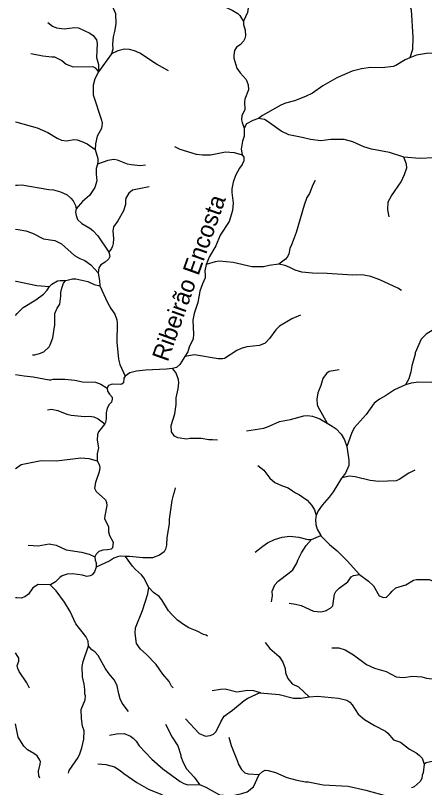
# Model space of a CAD drawing. Extents: x 500 to 555.2, y 9115.7 to 9171.
# Drawn here: x 500 to 504.79, y 9143.26 to 9152.3 of the extents above; entities that cross this region are included whole.
import ezdxf
from ezdxf.enums import TextEntityAlignment as Align

# ---------------------------------------------------------------- set-up
doc = ezdxf.new("R2010")
doc.units = 0
doc.header["$LTSCALE"] = 0.064
doc.layers.add('61', color=7, linetype='Continuous')
doc.layers.add('7', color=7, linetype='Continuous', lineweight=25)

msp = doc.modelspace()

# ---------------------------------------------------------------- linework, layer by layer
at = {"layer": '7'}
for points in [[(500.9676, 9152.7694), (500.9701, 9152.7268), (500.9891, 9152.6569), (501.0168, 9152.5919), (501.1328, 9152.412), (501.1707, 9152.3228), (501.174, 9152.2009), (501.1611, 9152.1136), (501.1443, 9152.0512), (501.1349, 9151.966), (501.1379, 9151.9062), (501.1255, 9151.8512), (500.9703, 9151.6416)], [(501.9827, 9152.5119), (502.1534, 9152.577), (502.2129, 9152.5851), (502.2481, 9152.5782), (502.3137, 9152.5347), (502.4061, 9152.4214), (502.5362, 9152.3619), (502.6017, 9152.3224), (502.6273, 9152.2997), (502.6672, 9152.2303)], [(502.7408, 9152.507), (502.7145, 9152.3334), (502.6671, 9152.2321), (502.6672, 9152.2303)], [(504.5928, 9152.4699), (504.6303, 9152.3683), (504.6515, 9152.0479), (504.6464, 9151.9023), (504.6152, 9151.8029)], [(500.3777, 9152.2187), (500.4333, 9152.1733), (500.4787, 9152.154), (500.57, 9152.1426), (500.6954, 9152.1587), (500.7376, 9152.1538), (500.8713, 9152.0921), (500.9084, 9152.0668), (500.949, 9152.0133), (500.9573, 9151.9733), (500.9479, 9151.8073), (500.9737, 9151.7273), (500.9703, 9151.6416)], [(502.6672, 9152.2303), (502.6701, 9152.195), (502.6866, 9152.1287), (502.6911, 9152.0622), (502.6848, 9152.031), (502.668, 9152.0008), (502.63, 9151.9568), (502.5882, 9151.9274), (502.5635, 9151.8891), (502.5553, 9151.834), (502.5573, 9151.8001), (502.5924, 9151.6845), (502.6283, 9151.6302), (502.6994, 9151.5501), (502.7242, 9151.4883), (502.7257, 9151.4296), (502.6839, 9151.3205), (502.6787, 9151.289), (502.6863, 9151.1944), (502.6508, 9151.1274), (502.6473, 9151.0777)], [(501.7905, 9151.6527), (501.6488, 9151.7315), (501.4538, 9151.8598), (501.3929, 9151.8879), (501.3337, 9151.9026), (501.2778, 9151.9054), (501.1966, 9151.8862), (501.1255, 9151.8512)], [(500.1783, 9151.8533), (500.3212, 9151.8275), (500.4262, 9151.8161), (500.4574, 9151.8174), (500.5426, 9151.7717), (500.5936, 9151.7308), (500.6762, 9151.6983), (500.907, 9151.7012), (500.9325, 9151.6879), (500.9703, 9151.6416)], [(504.6152, 9151.8029), (504.5628, 9151.7813), (504.4519, 9151.7147), (504.4194, 9151.7046), (504.2913, 9151.6866), (504.1548, 9151.6895), (504.0498, 9151.6762), (503.9417, 9151.6497), (503.7622, 9151.5706), (503.5986, 9151.4764), (503.4766, 9151.3919), (503.3965, 9151.3524), (503.2645, 9151.2996), (503.1589, 9151.273), (503.1064, 9151.2517), (502.8904, 9151.1301), (502.8449, 9151.0937)], [(505.002, 9151.8631), (504.8109, 9151.8553), (504.6949, 9151.8358), (504.6152, 9151.8029)], [(500.9703, 9151.6416), (500.9283, 9151.5569), (500.9112, 9151.4854), (500.9085, 9151.3722), (501.0066, 9151.0736), (501.0134, 9151.0395), (501.0069, 9150.9753), (500.9561, 9150.8859), (500.9363, 9150.7967), (500.9345, 9150.7305)], [(502.6473, 9151.0777), (502.6523, 9151.046), (502.6757, 9150.9804)], [(502.8449, 9151.0937), (502.8437, 9151.0927), (502.7779, 9151.0692), (502.7035, 9151.0316), (502.6757, 9150.9804)], [(504.5464, 9150.6424), (504.5436, 9150.6427), (504.3793, 9150.6973), (504.1668, 9150.7341), (504.0768, 9150.7628), (503.9479, 9150.822), (503.8453, 9150.8463), (503.6904, 9150.8498), (503.573, 9150.8336), (503.4528, 9150.8468), (503.3563, 9150.8718), (503.1984, 9150.9024), (503.1087, 9150.9447), (502.9473, 9151.0631), (502.9129, 9151.081), (502.8449, 9151.0937)], [(499.9999, 9151.0557), (500.0144, 9151.0516), (500.2529, 9150.9841), (500.3803, 9150.9285), (500.488, 9150.8627), (500.5371, 9150.8403), (500.5968, 9150.8335), (500.688, 9150.8466), (500.7214, 9150.8433), (500.778, 9150.8261), (500.8382, 9150.7965), (500.9345, 9150.7305)], [(502.6757, 9150.9804), (502.6759, 9150.9798), (502.6764, 9150.8886), (502.6569, 9150.8296), (502.6407, 9150.735), (502.6545, 9150.6698)], [(505.423, 9150.9952), (505.3829, 9150.9655), (505.2722, 9150.9271), (505.2438, 9150.9105), (505.1424, 9150.8142), (505.0532, 9150.702), (505.0118, 9150.6693), (504.9632, 9150.6482), (504.9035, 9150.6352), (504.7294, 9150.6237), (504.5464, 9150.6424)], [(500.9345, 9150.7305), (500.9632, 9150.624), (500.9647, 9150.5935), (500.9596, 9150.5602)], [(501.8611, 9150.7678), (501.9222, 9150.7335), (502.1164, 9150.6782), (502.1906, 9150.668), (502.2836, 9150.6703), (502.4601, 9150.7055), (502.5593, 9150.6939), (502.6545, 9150.6698)], [(501.5228, 9150.5473), (501.4629, 9150.5415), (501.3526, 9150.5511), (501.3125, 9150.561), (501.1932, 9150.6057), (501.1519, 9150.6135), (501.08, 9150.6032), (500.9596, 9150.5602)], [(502.6545, 9150.6698), (502.6717, 9150.6429), (502.6717, 9150.599), (502.6526, 9150.5559), (502.6226, 9150.512), (502.5764, 9150.4261), (502.547, 9150.3473), (502.5324, 9150.2692), (502.5324, 9150.2291), (502.5471, 9150.1019), (502.5403, 9150.016), (502.5002, 9149.8872), (502.3971, 9149.7264), (502.3463, 9149.6017), (502.2707, 9149.4768), (502.2323, 9149.384)], [(504.3736, 9149.9422), (504.358, 9150.0251), (504.3628, 9150.1177), (504.4015, 9150.1894), (504.5144, 9150.3507), (504.5527, 9150.4386), (504.5792, 9150.5172), (504.5775, 9150.5587), (504.5464, 9150.6424)], [(500.9596, 9150.5602), (500.9437, 9150.5101), (500.9446, 9150.4438), (500.9542, 9150.365), (500.9284, 9150.2862), (500.8647, 9150.1942), (500.7834, 9150.1211), (500.7111, 9150.0378)], [(503.5091, 9150.3673), (503.4793, 9150.3179), (503.441, 9150.2173), (503.4114, 9150.1686), (503.3774, 9150.08), (503.2837, 9149.7598), (503.2487, 9149.6672), (503.2313, 9149.6139), (503.2113, 9149.5698), (503.1998, 9149.5049), (503.1819, 9149.4721), (503.1589, 9149.4459), (503.0828, 9149.3887)], [(499.9999, 9150.3125), (500.0242, 9150.3138), (500.0743, 9150.3165), (500.3895, 9150.2633), (500.4459, 9150.2593), (500.527, 9150.237), (500.6033, 9150.2003), (500.6499, 9150.162), (500.6771, 9150.1296), (500.7014, 9150.0762), (500.7111, 9150.0378)], [(501.5656, 9150.2941), (501.3688, 9150.2547), (501.325, 9150.2211), (501.2926, 9150.1614), (501.2874, 9150.1342), (501.2888, 9150.0872), (501.2652, 9150.0116), (501.1977, 9149.8961), (501.1485, 9149.8249), (501.1414, 9149.7786), (501.1479, 9149.6892), (501.1444, 9149.6289), (501.1365, 9149.5974), (501.1243, 9149.5697), (501.0943, 9149.5292)], [(500.7111, 9150.0378), (500.7036, 9149.9961), (500.7101, 9149.9576), (500.727, 9149.9131), (500.7778, 9149.8653), (500.8718, 9149.8087), (500.9063, 9149.7809), (500.9636, 9149.7183), (501.0943, 9149.5292)], [(499.9999, 9149.7986), (500.0303, 9149.794), (500.1217, 9149.7801), (500.1992, 9149.7495), (500.3273, 9149.6833), (500.4623, 9149.6638), (500.5404, 9149.6281), (500.6925, 9149.4881), (500.7517, 9149.4538), (500.8106, 9149.4306), (500.882, 9149.3813), (500.9675, 9149.2848)], [(501.0943, 9149.5292), (501.1032, 9149.4761), (501.0908, 9149.4469), (501.0492, 9149.4098), (500.9991, 9149.3816), (500.9744, 9149.3467), (500.9675, 9149.2848)], [(502.2323, 9149.384), (502.2159, 9149.3119), (502.2206, 9149.2588), (502.2185, 9149.2286), (502.1894, 9149.1589), (502.1572, 9149.0732), (502.135, 9148.9392), (502.0926, 9148.8087), (502.0767, 9148.732), (502.0853, 9148.5692), (502.0795, 9148.5129), (502.0342, 9148.4171), (502.0185, 9148.3626), (501.9831, 9148.308)], [(503.0828, 9149.3887), (502.9687, 9149.3736), (502.9024, 9149.3556), (502.7668, 9149.3586), (502.5461, 9149.4063), (502.3852, 9149.4229), (502.3383, 9149.4162), (502.2323, 9149.384)], [(504.5195, 9149.0783), (504.4738, 9149.1065), (504.2644, 9149.2063), (504.1596, 9149.244), (504.077, 9149.2588), (503.9955, 9149.2636), (503.943, 9149.2605), (503.6483, 9149.2801), (503.4759, 9149.2818), (503.3519, 9149.2949), (503.2717, 9149.3171), (503.2102, 9149.3511), (503.1562, 9149.3734), (503.0828, 9149.3887)], [(500.9675, 9149.2848), (500.9671, 9149.2814), (500.9837, 9149.1971), (500.9892, 9149.1336)], [(499.9999, 9149.1893), (500.0085, 9149.1875), (500.2487, 9149.1378), (500.3992, 9149.1249)], [(500.1982, 9148.3278), (500.2285, 9148.3279), (500.2818, 9148.3403), (500.3306, 9148.363), (500.3951, 9148.4207), (500.4081, 9148.4419), (500.4392, 9148.524), (500.4556, 9148.654), (500.4622, 9148.6722), (500.4605, 9148.8098), (500.4884, 9148.8744), (500.5196, 9148.9217), (500.5311, 9149.015), (500.5309, 9149.0567), (500.5412, 9149.1079), (500.5638, 9149.1638), (500.5882, 9149.1968)], [(500.3992, 9149.1249), (500.4018, 9149.1291), (500.4276, 9149.1539), (500.4929, 9149.1928), (500.5221, 9149.1981), (500.5882, 9149.1968)], [(500.5882, 9149.1968), (500.6684, 9149.2159), (500.705, 9149.2145), (500.8488, 9149.1868), (500.9199, 9149.1516), (500.9892, 9149.1336)], [(499.9999, 9148.7879), (500.0206, 9148.8098), (500.0888, 9148.8818), (500.2374, 9148.971), (500.3265, 9149.0378), (500.3728, 9149.0823), (500.3992, 9149.1249)], [(500.9892, 9149.1336), (501.0782, 9148.9392), (501.1171, 9148.8679), (501.1617, 9148.8014), (501.1856, 9148.7372), (501.1923, 9148.6968), (501.1879, 9148.4754), (501.2071, 9148.2764), (501.2233, 9148.2124), (501.2827, 9148.0783)], [(503.3352, 9148.7913), (503.235, 9148.7473), (503.091, 9148.6625), (503.046, 9148.6206), (502.9739, 9148.5163), (502.9218, 9148.4644), (502.8572, 9148.435), (502.7067, 9148.4189), (502.6416, 9148.3996), (502.5905, 9148.3757), (502.4476, 9148.2825), (502.4221, 9148.2779), (502.3736, 9148.2809), (502.0973, 9148.327), (501.9831, 9148.308)], [(505.1435, 9148.6389), (505.102, 9148.636), (505.042, 9148.6404), (504.9278, 9148.6306), (504.8878, 9148.6174), (504.8059, 9148.5682), (504.7492, 9148.5086), (504.6799, 9148.3507), (504.6793, 9148.3332), (504.6383, 9148.1985), (504.6283, 9148.1265), (504.6057, 9148.0456), (504.5646, 9147.9763)], [(501.9831, 9148.308), (501.9221, 9148.214), (501.8862, 9148.178), (501.8361, 9148.1671)], [(499.9999, 9148.0957), (500.1037, 9148.0825), (500.2058, 9148.0695), (500.3934, 9148.0352), (500.4159, 9148.0352), (500.4432, 9148.0433), (500.5786, 9148.0433), (500.6959, 9148.03), (500.7839, 9148.0106), (500.9374, 9148.0072), (500.9997, 9147.9846), (501.0722, 9147.9381)], [(501.2827, 9148.0783), (501.2703, 9148.0522), (501.2631, 9147.9999), (501.2461, 9147.9847), (501.2243, 9147.9795), (501.1324, 9147.984), (501.0881, 9147.9656), (501.0717, 9147.9407), (501.0722, 9147.9381)], [(501.8361, 9148.1671), (501.7683, 9148.1606), (501.5205, 9148.1465), (501.4155, 9148.1333), (501.3389, 9148.1156), (501.2827, 9148.0783)], [(502.3651, 9147.3266), (502.3048, 9147.3331), (502.2628, 9147.3315), (502.1727, 9147.3461), (502.0391, 9147.3461), (502.004, 9147.3397), (501.8987, 9147.3531), (501.8632, 9147.3726), (501.8269, 9147.4231), (501.8206, 9147.5004), (501.8661, 9147.6368), (501.8793, 9147.7432), (501.8828, 9147.8213), (501.9041, 9147.9269), (501.9107, 9147.9994), (501.9088, 9148.039), (501.8787, 9148.1199), (501.8361, 9148.1671)], [(503.7881, 9148.1506), (503.6718, 9148.1322), (503.6387, 9148.1096), (503.5967, 9148.0477), (503.5755, 9147.9685), (503.5378, 9147.8803), (503.5264, 9147.8089), (503.5316, 9147.7459), (503.5397, 9147.7199), (503.6464, 9147.5276)], [(505.6399, 9148.0419), (505.5445, 9148.027), (505.1508, 9148.0171), (504.8696, 9148.0008), (504.7191, 9148.0055), (504.6319, 9147.9941), (504.5646, 9147.9763)], [(501.0722, 9147.9381), (501.0788, 9147.9001), (501.1001, 9147.8644), (501.1324, 9147.8315), (501.1332, 9147.8062), (501.1231, 9147.7729), (501.0975, 9147.7436), (501.0717, 9147.7013), (501.0611, 9147.6454), (501.0626, 9147.5824), (501.0544, 9147.5333), (501.0445, 9147.5203)], [(504.5646, 9147.9763), (504.4352, 9147.9154), (504.3307, 9147.8469), (504.2587, 9147.8071), (504.1985, 9147.7608), (504.1063, 9147.6296), (503.9656, 9147.4735), (503.9313, 9147.4047), (503.8768, 9147.2546)], [(500.3759, 9147.6841), (500.42, 9147.6907), (500.4951, 9147.6758), (500.6002, 9147.6333), (500.6532, 9147.6201), (500.8061, 9147.6055), (500.8625, 9147.6085), (500.9156, 9147.6002), (500.9687, 9147.5783), (501.0445, 9147.5203)], [(502.7054, 9147.4358), (502.9063, 9147.4693), (502.9686, 9147.4902), (503.0908, 9147.546), (503.2174, 9147.5691), (503.3739, 9147.6105), (503.4165, 9147.6143), (503.4774, 9147.6089), (503.561, 9147.5765), (503.6464, 9147.5276)], [(501.0445, 9147.5203), (500.9716, 9147.4245), (500.9595, 9147.3931), (500.9544, 9147.3272), (500.9706, 9147.2393), (500.9545, 9147.1665), (500.9582, 9147.0852)], [(503.6464, 9147.5276), (503.7079, 9147.4924), (503.7521, 9147.4596), (503.8117, 9147.3987), (503.8495, 9147.3331), (503.8768, 9147.2546)], [(503.8768, 9147.2546), (503.9036, 9147.0936), (503.9004, 9147.0287), (503.8625, 9146.9395), (503.8202, 9146.8862)], [(499.9999, 9146.9929), (500.0082, 9146.9991), (500.0651, 9147.0415), (500.3001, 9147.0902), (500.4787, 9147.0838), (500.7644, 9147.1199), (500.86, 9147.1137), (500.9582, 9147.0852)], [(500.9582, 9147.0852), (500.9805, 9147.0405), (500.9887, 9147.0069), (500.9807, 9146.9565), (500.9349, 9146.8318), (500.925, 9146.7644), (500.9429, 9146.7264), (501.0549, 9146.6273), (501.0655, 9146.5965), (501.069, 9146.5622), (501.0464, 9146.4422), (501.0431, 9146.4081), (501.087, 9146.3128), (501.0889, 9146.2545), (501.1001, 9146.2123), (501.1444, 9146.1337), (501.1364, 9146.0657), (501.1206, 9146.0519), (501.0784, 9146.0423), (501.024, 9146.039), (500.9744, 9146.0233), (500.9432, 9145.9939), (500.9299, 9145.9604)], [(502.8367, 9147.0321), (502.9063, 9146.9755), (502.9788, 9146.8833), (503.0343, 9146.8329), (503.1125, 9146.7953), (503.1913, 9146.7674), (503.2442, 9146.7359), (503.276, 9146.7095), (503.323, 9146.6879), (503.4136, 9146.6239), (503.4685, 9146.5611), (503.4999, 9146.511), (503.5198, 9146.4449)], [(504.6761, 9146.9763), (504.603, 9146.9397), (504.4903, 9146.867), (504.4574, 9146.8526), (504.2534, 9146.8443), (504.1513, 9146.854), (503.9751, 9146.8995), (503.9085, 9146.9064), (503.8202, 9146.8862)], [(503.8202, 9146.8862), (503.8158, 9146.8807), (503.7203, 9146.7235), (503.6719, 9146.6584), (503.5899, 9146.5649), (503.5431, 9146.5012), (503.5198, 9146.4449)], [(501.8711, 9146.7697), (501.8534, 9146.7043), (501.8482, 9146.7005), (501.8303, 9146.6206), (501.8008, 9146.4041), (501.7974, 9146.3457), (501.7714, 9146.1882), (501.7679, 9146.097), (501.7566, 9146.051), (501.7423, 9146.0201), (501.6859, 9145.9799), (501.6026, 9145.9502), (501.4891, 9145.9487), (501.3362, 9145.9648), (501.2897, 9145.9632)], [(503.5198, 9146.4449), (503.5126, 9146.3981), (503.5172, 9146.3381), (503.5313, 9146.2834), (503.5722, 9146.2107)], [(502.8067, 9146.0153), (502.8971, 9146.0874), (502.9517, 9146.1239), (503.0305, 9146.1633), (503.1223, 9146.193), (503.2095, 9146.2028), (503.318, 9146.1928), (503.4218, 9146.1657), (503.4651, 9146.1649)], [(502.9964, 9145.4336), (503.0079, 9145.5045), (503.0049, 9145.5577), (503.0356, 9145.6323), (503.0737, 9145.678), (503.2048, 9145.7736), (503.245, 9145.8102), (503.2931, 9145.8858), (503.3052, 9145.9229), (503.3489, 9146.0088), (503.4026, 9146.0936), (503.4651, 9146.1649), (503.5722, 9146.2107)], [(503.5722, 9146.2107), (503.5732, 9146.2089), (503.6751, 9146.1066), (503.767, 9146.0296), (503.8827, 9145.9154), (504.025, 9145.755)], [(500.1477, 9146.0976), (500.2649, 9146.0898), (500.3956, 9146.1126), (500.4765, 9146.0974), (500.5916, 9146.0428), (500.7717, 9146.0153), (500.8611, 9145.9926), (500.9299, 9145.9604)], [(500.9299, 9145.9604), (500.9325, 9145.9231), (500.9461, 9145.8896), (500.9454, 9145.8447), (500.9444, 9145.8415)], [(501.2897, 9145.9632), (501.2266, 9145.9682), (501.1955, 9145.9628), (501.1507, 9145.945), (501.1047, 9145.9155), (500.9444, 9145.8415)], [(501.5604, 9145.6038), (501.5038, 9145.7158), (501.476, 9145.7518), (501.4051, 9145.813), (501.3698, 9145.8514), (501.2897, 9145.9632)], [(500.9444, 9145.8415), (500.9262, 9145.7864), (500.8988, 9145.7523), (500.873, 9145.7375), (500.8341, 9145.7289), (500.7838, 9145.7469), (500.6657, 9145.7633), (500.6052, 9145.7596), (500.5482, 9145.7374), (500.5204, 9145.7205), (500.4668, 9145.6693), (500.4116, 9145.6325), (500.4078, 9145.6326)], [(503.203, 9145.4172), (503.277, 9145.4073), (503.3421, 9145.3895), (503.4891, 9145.3257), (503.5729, 9145.319), (503.628, 9145.3287), (503.6925, 9145.3622), (503.7133, 9145.3861), (503.7345, 9145.5226), (503.7515, 9145.5552), (503.7889, 9145.5931), (503.8917, 9145.6696), (503.9303, 9145.7259), (503.9567, 9145.7421), (504.025, 9145.755)], [(504.025, 9145.755), (504.1332, 9145.6764), (504.1907, 9145.6206), (504.2553, 9145.5029), (504.3089, 9145.4832), (504.3412, 9145.4902), (504.3838, 9145.53), (504.4076, 9145.5603), (504.4528, 9145.5972), (504.569, 9145.6352), (504.658, 9145.6866), (504.6948, 9145.6948), (504.8418, 9145.6959), (504.9075, 9145.6682), (504.9661, 9145.6302)], [(500.4078, 9145.6326), (500.2643, 9145.6368), (500.2052, 9145.5997), (500.1516, 9145.525)], [(500.8541, 9144.9183), (500.8492, 9144.9739), (500.8248, 9145.0301), (500.7084, 9145.1778), (500.6411, 9145.3221), (500.575, 9145.4309), (500.4775, 9145.5611), (500.4078, 9145.6326)], [(501.8457, 9144.4271), (501.8273, 9144.4483), (501.7979, 9144.5014), (501.7256, 9144.589), (501.6449, 9144.7021), (501.5317, 9144.8218), (501.4653, 9144.8801), (501.4184, 9144.9478), (501.4022, 9145.0679), (501.404, 9145.1285), (501.4869, 9145.3338), (501.5498, 9145.5289), (501.5604, 9145.6038)], [(502.249, 9145.0327), (502.2309, 9145.0434), (502.2008, 9145.0498), (502.1266, 9145.0903), (502.0287, 9145.131), (501.9681, 9145.1674), (501.8984, 9145.2195), (501.8294, 9145.2852), (501.7931, 9145.3301), (501.7142, 9145.4561), (501.6829, 9145.4955), (501.6169, 9145.545), (501.5604, 9145.6038)], [(500.1516, 9145.525), (500.1109, 9145.4913), (500.068, 9145.4779), (500.0145, 9145.4813), (499.9999, 9145.4822)], [(500.6199, 9143.4298), (500.6278, 9143.4583), (500.7326, 9143.6124), (500.7542, 9143.6524), (500.7773, 9143.725), (500.7986, 9143.8268), (500.8034, 9143.924), (500.7854, 9143.9778), (500.7713, 9144.068), (500.7674, 9144.1728), (500.8162, 9144.2881), (500.8216, 9144.3323), (500.8134, 9144.3518), (500.8132, 9144.4083), (500.8051, 9144.4691), (500.7839, 9144.5571), (500.7806, 9144.6758), (500.7928, 9144.7374), (500.8541, 9144.9183)], [(501.3229, 9144.1494), (501.2497, 9144.2494), (501.2269, 9144.298), (501.2086, 9144.3583), (501.1911, 9144.4506), (501.1576, 9144.5182), (501.0931, 9144.5932), (501.0483, 9144.6573), (500.9676, 9144.807), (500.9302, 9144.8493), (500.8939, 9144.874), (500.8541, 9144.9183)], [(502.9214, 9144.9598), (502.9773, 9144.887), (503.0846, 9144.7927), (503.1295, 9144.7293), (503.1555, 9144.6529), (503.1597, 9144.6016), (503.1882, 9144.5369), (503.239, 9144.4747), (503.3137, 9144.4395), (503.4377, 9144.3228)], [(500.1639, 9144.4219), (500.1329, 9144.485), (500.0428, 9144.6195), (500.028, 9144.6523), (500.0211, 9144.6897), (500.0389, 9144.7382), (500.0391, 9144.7741), (500.0277, 9144.7923), (499.9999, 9144.8367)], [(503.7022, 9144.8967), (503.7849, 9144.8972), (503.8577, 9144.871), (503.9561, 9144.812), (504.1081, 9144.6991), (504.2008, 9144.6572), (504.3401, 9144.619), (504.457, 9144.5544), (504.5433, 9144.5479), (504.6465, 9144.5643), (504.7566, 9144.5576), (504.8121, 9144.5407), (504.9075, 9144.5281), (504.9691, 9144.5042), (505.0419, 9144.4301)], [(501.9882, 9144.0637), (502.1497, 9143.8906), (502.226, 9143.8593), (502.2803, 9143.8674), (502.3169, 9143.8865), (502.3502, 9143.9148), (502.4044, 9144.0295), (502.4422, 9144.0952), (502.5405, 9144.1657), (502.6784, 9144.2805), (502.7178, 9144.3051), (502.8636, 9144.3709)], [(502.3028, 9144.3975), (502.4017, 9144.4133), (502.4548, 9144.4149), (502.5891, 9144.3805), (502.7178, 9144.4017), (502.7857, 9144.3966), (502.8636, 9144.3709)], [(502.8636, 9144.3709), (502.8647, 9144.3705), (503.0867, 9144.351), (503.2536, 9144.308), (503.342, 9144.3067), (503.4377, 9144.3228)], [(503.4377, 9144.3228), (503.5369, 9144.3313), (503.7802, 9144.3045), (503.8767, 9144.2839), (503.9134, 9144.2575), (503.9408, 9144.2285), (504.0119, 9144.1182), (504.0844, 9144.0564), (504.2002, 9143.986), (504.3295, 9143.9216), (504.3595, 9143.895), (504.4249, 9143.8184), (504.5045, 9143.7896), (504.6108, 9143.7107), (504.6909, 9143.6654), (504.7248, 9143.6395), (504.7584, 9143.6024), (504.7835, 9143.5318)], [(500.2835, 9143.3697), (500.2723, 9143.3986), (500.2704, 9143.4502), (500.2902, 9143.5329), (500.2917, 9143.5631), (500.2864, 9143.5806), (500.2523, 9143.6293), (500.2133, 9143.6591), (500.1414, 9143.7011), (500.0967, 9143.7426), (500.0309, 9143.8486), (500.0195, 9143.9066), (499.9999, 9144.0063)], [(501.7575, 9144.0018), (501.8327, 9143.848), (501.9004, 9143.748), (501.9351, 9143.6392), (501.9359, 9143.6216), (501.9625, 9143.5537), (502.0002, 9143.4796), (502.0917, 9143.3812), (502.1551, 9143.2942)], [(501.1011, 9143.8726), (501.184, 9143.8901), (501.273, 9143.8934), (501.3448, 9143.8621), (501.3759, 9143.8392), (501.412, 9143.8015), (501.4489, 9143.7466), (501.5953, 9143.5937), (501.7249, 9143.4774), (501.929, 9143.3301), (501.9688, 9143.3076), (502.0169, 9143.2913), (502.1551, 9143.2942)], [(502.4986, 9143.851), (502.523, 9143.7506), (502.6022, 9143.5559), (502.6053, 9143.5357), (502.6458, 9143.4706), (502.6864, 9143.4313), (502.7234, 9143.4194), (502.8542, 9143.412)], [(505.0832, 9143.8349), (505.0235, 9143.7798), (504.9881, 9143.7338), (504.9701, 9143.6308), (504.9494, 9143.604), (504.8943, 9143.5703), (504.8049, 9143.5493), (504.7835, 9143.5318)], [(500.9643, 9143.5366), (501.0579, 9143.5305), (501.1576, 9143.5029), (501.2267, 9143.4603), (501.2676, 9143.4228), (501.4187, 9143.3194), (501.5573, 9143.2411), (501.7002, 9143.1826), (501.8179, 9143.119), (501.959, 9143.0594), (502.0573, 9143.0566), (502.1503, 9143.0247), (502.1825, 9143.0017), (502.31, 9142.8774)], [(504.7835, 9143.5318), (504.7727, 9143.4336), (504.7616, 9143.403), (504.7564, 9143.367), (504.7373, 9143.3297), (504.6675, 9143.2695), (504.637, 9143.2549), (504.6357, 9143.2548)], [(502.1551, 9143.2942), (502.2264, 9143.2652), (502.3865, 9143.1751), (502.5297, 9143.1636), (502.6498, 9143.1896), (502.7101, 9143.2098), (502.7848, 9143.2671), (502.8536, 9143.4115), (502.8542, 9143.412)], [(502.8542, 9143.412), (502.8891, 9143.4424), (502.9235, 9143.4619), (502.9561, 9143.4585), (503.0448, 9143.4339), (503.1768, 9143.3778), (503.2922, 9143.3451), (503.3952, 9143.3276), (503.4261, 9143.3272), (503.6025, 9143.2914), (503.8938, 9143.275), (504.1004, 9143.2307), (504.3557, 9143.1571), (504.3933, 9143.1335), (504.4178, 9143.1014)]]:
    msp.add_lwpolyline(points, dxfattribs=at)

# ---------------------------------------------------------------- texts
at = {"layer": '61'}
msp.add_text('Ribeirão Encosta', height=0.2, rotation=70.408, dxfattribs=at).set_placement((502.1234, 9149.1957), align=Align.CENTER)

doc.saveas('drawing.dxf')
